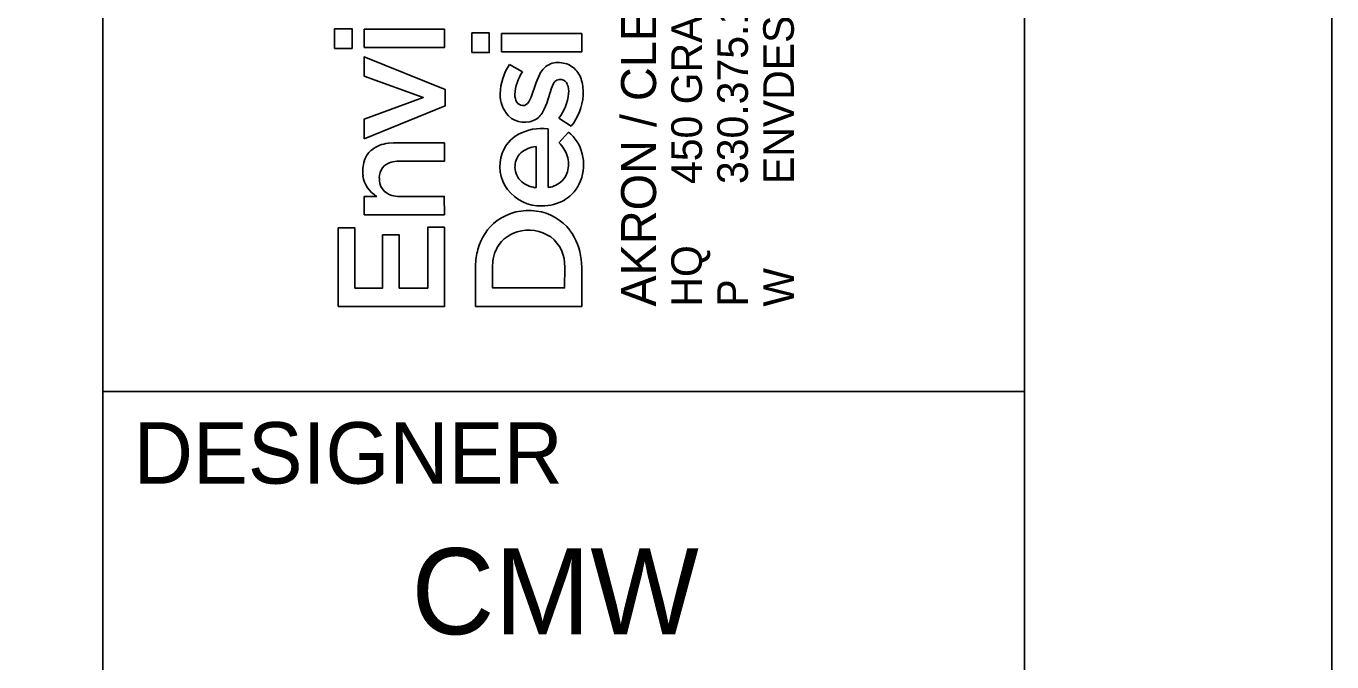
# Model space of a CAD drawing. Extents: x 0 to 1700, y 0 to 1100.
# Drawn here: x 1593.8 to 1700, y 103 to 154.7 of the extents above; entities that cross this region are included whole.
import ezdxf

# ---------------------------------------------------------------- set-up
doc = ezdxf.new("R2010")
doc.units = 0
for name, color, linetype in [('SH_Border', 7, 'Continuous'), ('SH_Cut_Line', 7, 'Continuous'), ('SH_Data', 7, 'Continuous')]:
    doc.layers.add(name, color=color, linetype=linetype)

msp = doc.modelspace()

# ---------------------------------------------------------------- linework, layer by layer
at = {"layer": 'SH_Border'}
for p, q in [((1600, 25), (1600, 1075)), ((1600, 125), (1675, 125))]:
    msp.add_line(p, q, dxfattribs=at)
msp.add_lwpolyline([(75, 1075), (1675, 1075), (1675, 25), (75, 25)], close=True, dxfattribs=at)
at = {"layer": 'SH_Cut_Line'}
msp.add_lwpolyline([(0, 0), (1700, 0), (1700, 1100), (0, 1100)], close=True, dxfattribs=at)
at = {"layer": 'SH_Data'}
for p, q in [((1618.85, 152.91), (1618.85, 154.51)), ((1618.85, 154.51), (1620.27, 154.51)), ((1620.27, 154.51), (1620.27, 152.91)), ((1621.27, 152.97), (1621.27, 154.46)), ((1621.27, 154.46), (1627.79, 154.46)), ((1627.79, 154.46), (1627.79, 152.97)), ((1630.03, 152.56), (1630.03, 154.16)), ((1630.03, 154.16), (1631.44, 154.16)), ((1631.44, 154.16), (1631.44, 152.56)), ((1632.44, 152.62), (1632.44, 154.11)), ((1632.44, 154.11), (1638.96, 154.11)), ((1638.96, 154.11), (1638.96, 152.62)), ((1620.27, 152.91), (1618.85, 152.91)), ((1627.79, 152.97), (1621.27, 152.97)), ((1621.27, 150.66), (1621.27, 152.23)), ((1621.27, 152.23), (1627.84, 149.57)), ((1631.44, 152.56), (1630.03, 152.56)), ((1638.96, 152.62), (1632.44, 152.62)), ((1633.08, 151.6), (1634.13, 151.01)), ((1626.06, 148.9), (1621.27, 150.66)), ((1634.84, 148.93), (1635.24, 150.13)), ((1635.24, 150.13), (1635.52, 150.76)), ((1636.67, 150.05), (1636.49, 149.67)), ((1621.27, 147.15), (1626.06, 148.9)), ((1627.84, 149.57), (1627.84, 148.22)), ((1634.65, 148.56), (1634.84, 148.93)), ((1636.49, 149.67), (1636.11, 148.44)), ((1627.84, 148.22), (1621.27, 145.54)), ((1636.11, 148.44), (1635.91, 147.96)), ((1621.27, 145.54), (1621.27, 147.15)), ((1638.11, 146.57), (1637.1, 147.23)), ((1636.23, 146.37), (1636.23, 141.6)), ((1637.11, 145.23), (1637.88, 146.1)), ((1623.22, 145.2), (1623.64, 145.22)), ((1623.64, 145.22), (1627.79, 145.22)), ((1627.79, 145.22), (1627.79, 143.73)), ((1635.24, 141.59), (1635.24, 144.92)), ((1627.79, 143.73), (1624.07, 143.73)), ((1635.18, 141.58), (1635.24, 141.59)), ((1621.27, 140.86), (1622.28, 140.87)), ((1621.27, 139.37), (1621.27, 140.86)), ((1624.11, 140.87), (1627.78, 140.87)), ((1627.78, 140.87), (1627.79, 139.38)), ((1627.79, 139.38), (1621.27, 139.37)), ((1619.15, 131.9), (1619.15, 138.3)), ((1619.15, 138.3), (1620.51, 138.3)), ((1620.51, 138.3), (1620.51, 133.41)), ((1626.43, 133.41), (1626.43, 138.36)), ((1626.43, 138.36), (1627.79, 138.36)), ((1627.79, 138.36), (1627.79, 131.9)), ((1622.75, 133.41), (1622.75, 137.74)), ((1622.75, 137.74), (1624.11, 137.74)), ((1624.11, 137.74), (1624.11, 133.41)), ((1630.32, 131.9), (1630.32, 135.2)), ((1631.73, 135.59), (1631.7, 135.12)), ((1631.7, 135.12), (1631.7, 133.42)), ((1637.57, 133.42), (1637.58, 135.12)), ((1638.92, 135.75), (1638.96, 135.1)), ((1638.96, 135.1), (1638.96, 131.9)), ((1620.51, 133.41), (1622.75, 133.41)), ((1624.11, 133.41), (1626.43, 133.41)), ((1631.7, 133.42), (1637.57, 133.42)), ((1627.79, 131.9), (1619.15, 131.9)), ((1638.96, 131.9), (1630.32, 131.9))]:
    msp.add_line(p, q, dxfattribs=at)
for points in [[(1618.85, 152.91), (1618.85, 154.51), (1620.27, 154.51), (1620.27, 152.91)], [(1621.27, 152.97), (1621.27, 154.46), (1627.79, 154.46), (1627.79, 152.97)], [(1630.03, 152.56), (1630.03, 154.16), (1631.44, 154.16), (1631.44, 152.56)], [(1632.44, 152.62), (1632.44, 154.11), (1638.96, 154.11), (1638.96, 152.62)], [(1621.27, 145.54), (1621.27, 147.15), (1626.06, 148.9), (1621.27, 150.66), (1621.27, 152.23), (1627.84, 149.57), (1627.84, 148.22)], [(1619.15, 131.9), (1619.15, 138.3), (1620.51, 138.3), (1620.51, 133.41), (1622.75, 133.41), (1622.75, 137.74), (1624.11, 137.74), (1624.11, 133.41), (1626.43, 133.41), (1626.43, 138.36), (1627.79, 138.36), (1627.79, 131.9)]]:
    msp.add_lwpolyline(points, close=True, dxfattribs=at)
for points in [[(1633.08, 151.6), (1634.13, 151.01)], [(1634.65, 148.56), (1634.84, 148.93), (1635.24, 150.13), (1635.52, 150.76)], [(1636.67, 150.05), (1636.49, 149.67), (1636.11, 148.44), (1635.91, 147.96)], [(1638.11, 146.57), (1637.1, 147.23)], [(1636.23, 146.37), (1636.23, 141.6)], [(1637.11, 145.23), (1637.88, 146.1)], [(1623.22, 145.2), (1623.64, 145.22), (1627.79, 145.22), (1627.79, 143.73), (1624.07, 143.73)], [(1635.18, 141.58), (1635.24, 141.59), (1635.24, 144.92)], [(1621.27, 139.37), (1621.27, 140.86), (1622.28, 140.87)], [(1624.11, 140.87), (1627.78, 140.87), (1627.79, 139.38), (1621.27, 139.37)], [(1638.92, 135.75), (1638.96, 135.1), (1638.96, 131.9), (1630.32, 131.9)], [(1630.32, 131.9), (1630.32, 135.2)], [(1631.73, 135.59), (1631.7, 135.12), (1631.7, 133.42), (1637.57, 133.42), (1637.58, 135.12)]]:
    msp.add_lwpolyline(points, dxfattribs=at)
for centre, radius, start, end in [((1636.82, 149.13), 4.49, 146.531, 178.7571), ((1636.82, 149.13), 4.49, 146.531, 178.7571), ((1637.26, 148.94), 3.75, 146.5112, 176.9101), ((1637.26, 148.94), 3.75, 146.5112, 176.9101), ((1637.33, 149.86), 2.03, 125.5118, 153.4159), ((1637.33, 149.86), 2.03, 125.5118, 153.4159), ((1637.03, 150.13), 1.63, 80.1719, 122.5197), ((1637.03, 150.13), 1.63, 80.1719, 122.5197), ((1637.14, 149.91), 1.83, 47.7934, 84.6892), ((1637.14, 149.91), 1.83, 47.7934, 84.6892), ((1636.89, 149.73), 2.13, 14.9966, 46.2063), ((1636.89, 149.73), 2.13, 14.9966, 46.2063), ((1637.19, 149.82), 0.571, 76.6609, 155.7053), ((1637.19, 149.82), 0.571, 76.6609, 155.7053), ((1637.2, 149.76), 0.628, 21.5098, 78.5262), ((1637.2, 149.76), 0.628, 21.5098, 78.5262), ((1636.3, 149.38), 1.6, 354.5726, 22.068), ((1636.3, 149.38), 1.6, 354.5726, 22.068), ((1635.52, 149.34), 3.56, 355.8306, 15.3914), ((1635.52, 149.34), 3.56, 355.8306, 15.3914), ((1634.83, 149.12), 2.5, 177.5366, 222.7932), ((1634.83, 149.12), 2.5, 177.5366, 222.7932), ((1634.66, 149.12), 1.14, 178.4747, 211.0868), ((1634.66, 149.12), 1.14, 178.4747, 211.0868), ((1634.12, 149.57), 3.78, 321.811, 354.7969), ((1634.12, 149.57), 3.78, 321.811, 354.7969), ((1634.48, 149.41), 4.61, 321.9777, 355.8738), ((1634.48, 149.41), 4.61, 321.9777, 355.8738), ((1634.17, 148.83), 0.574, 212.2368, 268.3777), ((1634.17, 148.83), 0.574, 212.2368, 268.3777), ((1634.17, 148.79), 0.534, 267.716, 333.7337), ((1634.17, 148.79), 0.534, 267.716, 333.7337), ((1634.05, 148.79), 2.04, 308.0877, 335.9874), ((1634.05, 148.79), 2.04, 308.0877, 335.9874), ((1634.3, 148.77), 1.88, 225.9854, 302.4797), ((1634.3, 148.77), 1.88, 225.9854, 302.4797), ((1635.12, 143.45), 2.79, 118.8308, 160.6244), ((1635.12, 143.45), 2.79, 118.8308, 160.6244), ((1635.76, 142.21), 4.19, 83.615, 118.2876), ((1635.76, 142.21), 4.19, 83.615, 118.2876), ((1635.87, 143.58), 3.22, 13.5336, 51.3615), ((1635.87, 143.58), 3.22, 13.5336, 51.3615), ((1623.17, 143.13), 2.01, 132.2219, 161.6818), ((1623.17, 143.13), 2.01, 132.2219, 161.6818), ((1623.44, 142.71), 2.49, 94.9696, 130.2225), ((1623.44, 142.71), 2.49, 94.9696, 130.2225), ((1635.39, 142.8), 2.12, 94.008, 130.8817), ((1635.39, 142.8), 2.12, 94.008, 130.8817), ((1635.19, 143.28), 2.74, 19.0357, 45.4406), ((1635.19, 143.28), 2.74, 19.0357, 45.4406), ((1623.94, 142.91), 2.8, 162.2736, 187.7919), ((1623.94, 142.91), 2.8, 162.2736, 187.7919), ((1623.74, 142.43), 1.25, 103.6865, 182.2187), ((1623.74, 142.43), 1.25, 103.6865, 182.2187), ((1624.05, 141.43), 2.3, 89.6049, 105.3284), ((1624.05, 141.43), 2.3, 89.6049, 105.3284), ((1635.52, 143.31), 3.22, 160.5201, 215.7831), ((1635.52, 143.31), 3.22, 160.5201, 215.7831), ((1635.02, 143.31), 1.49, 132.9851, 177.179), ((1635.02, 143.31), 1.49, 132.9851, 177.179), ((1635.53, 143.49), 2.35, 344.6059, 17.007), ((1635.53, 143.49), 2.35, 344.6059, 17.007), ((1635.32, 143.46), 3.79, 339.3542, 13.3785), ((1635.32, 143.46), 3.79, 339.3542, 13.3785), ((1623.51, 142.9), 2.38, 188.962, 238.7037), ((1623.51, 142.9), 2.38, 188.962, 238.7037), ((1623.87, 142.28), 1.38, 175.5854, 255.1439), ((1623.87, 142.28), 1.38, 175.5854, 255.1439), ((1635.09, 143.25), 1.56, 175.0013, 223.283), ((1635.09, 143.25), 1.56, 175.0013, 223.283), ((1636.12, 143.36), 1.75, 288.0077, 343.5508), ((1636.12, 143.36), 1.75, 288.0077, 343.5508), ((1635.63, 143.53), 3.44, 217.7452, 271.6543), ((1635.63, 143.53), 3.44, 217.7452, 271.6543), ((1635.45, 143.68), 2.12, 225.0619, 262.7974), ((1635.45, 143.68), 2.12, 225.0619, 262.7974), ((1636.24, 142.61), 1.01, 269.7003, 294.8711), ((1636.24, 142.61), 1.01, 269.7003, 294.8711), ((1635.95, 143.26), 3.13, 300.9427, 338.7323), ((1635.95, 143.26), 3.13, 300.9427, 338.7323), ((1624.09, 142.97), 2.11, 254.0916, 270.5284), ((1624.09, 142.97), 2.11, 254.0916, 270.5284), ((1635.77, 143.62), 3.53, 269.2048, 300.3341), ((1635.77, 143.62), 3.53, 269.2048, 300.3341), ((1634.61, 135.4), 4.32, 81.194, 125.9984), ((1634.61, 135.4), 4.32, 81.194, 125.9984), ((1634.73, 135.57), 4.14, 37.8521, 82.402), ((1634.73, 135.57), 4.14, 37.8521, 82.402), ((1634.69, 135.45), 4.33, 127.2362, 165.148), ((1634.69, 135.45), 4.33, 127.2362, 165.148), ((1634.64, 134.93), 3.19, 55.6727, 107.2093), ((1634.64, 134.93), 3.19, 55.6727, 107.2093), ((1634.45, 135.39), 2.7, 106.1881, 157.3861), ((1634.45, 135.39), 2.7, 106.1881, 157.3861), ((1634.65, 135.25), 2.93, 357.4662, 52.2665), ((1634.65, 135.25), 2.93, 357.4662, 52.2665), ((1634.29, 135.28), 4.65, 5.7333, 37.304), ((1634.29, 135.28), 4.65, 5.7333, 37.304), ((1635.71, 135.14), 5.39, 164.7861, 179.3704), ((1635.71, 135.14), 5.39, 164.7861, 179.3704), ((1634.91, 135.19), 3.21, 157.3571, 172.9275), ((1634.91, 135.19), 3.21, 157.3571, 172.9275)]:
    msp.add_arc(centre, radius, start, end, dxfattribs=at)

# ---------------------------------------------------------------- texts
for s, height, p in [('450 GRANT ST., AKRON, OH  44311', 2.4923, (1648.74, 141.87)), ('AKRON / CLEVELAND / COLUMBUS', 2.8485, (1645.01, 131.9)), ('ENVDESIGNGROUP.COM', 2.4923, (1656.22, 141.87)), ('330.375.1390', 2.4923, (1652.48, 141.87)), ('HQ ', 2.492, (1648.74, 131.9)), ('W', 2.49, (1656.22, 131.9)), ('P', 2.49, (1652.48, 131.9))]:
    msp.add_text(s, height=height, rotation=90, dxfattribs=at).set_placement(p)
for s, height, p in [('DESIGNER', 5, (1602.5, 117.5)), ('CMW', 7, (1625.1, 105.25))]:
    msp.add_text(s, height=height, dxfattribs=at).set_placement(p)

doc.saveas('drawing.dxf')
